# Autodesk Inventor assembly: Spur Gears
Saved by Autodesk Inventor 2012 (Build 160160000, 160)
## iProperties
Created: 2011-12
Part Number: Spur Gears
Document SubType Name: Assembly
Designer: Admin
Categories: <?xml version="1.0" encoding="UTF-16"?> <MemberInstance><Categories><FamilyTemplate/><ParamToTemplateMap><ParamToTemplate><ParamToTemplate CategoryParameter="//
ClientObjectVersion: 1
Author: Admin
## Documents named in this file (3)
- C:\CMU\Datasets\Session 6\Cluster Ex 1\Workspaces\Workspace\GearBox-A\Design Accelerator\Spur Gears3.iam
- C:\CMU\Datasets\Session 6\Cluster Ex 1\Workspaces\Workspace\GearBox-A\Design Accelerator\Spur Gear13.ipt
- C:\CMU\Datasets\Session 6\Cluster Ex 1\Workspaces\Workspace\GearBox-A\Design Accelerator\Spur Gear23.ipt
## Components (2 placed, 2 different names)
1. Spur Gear1:1 — Rotation:1
2. Spur Gear2:1 — Rotation:1
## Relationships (1: RelateRotation 1)
- Rotation:1 [RelateRotation]: Spur Gear1:1 ↔ Spur Gear2:1
